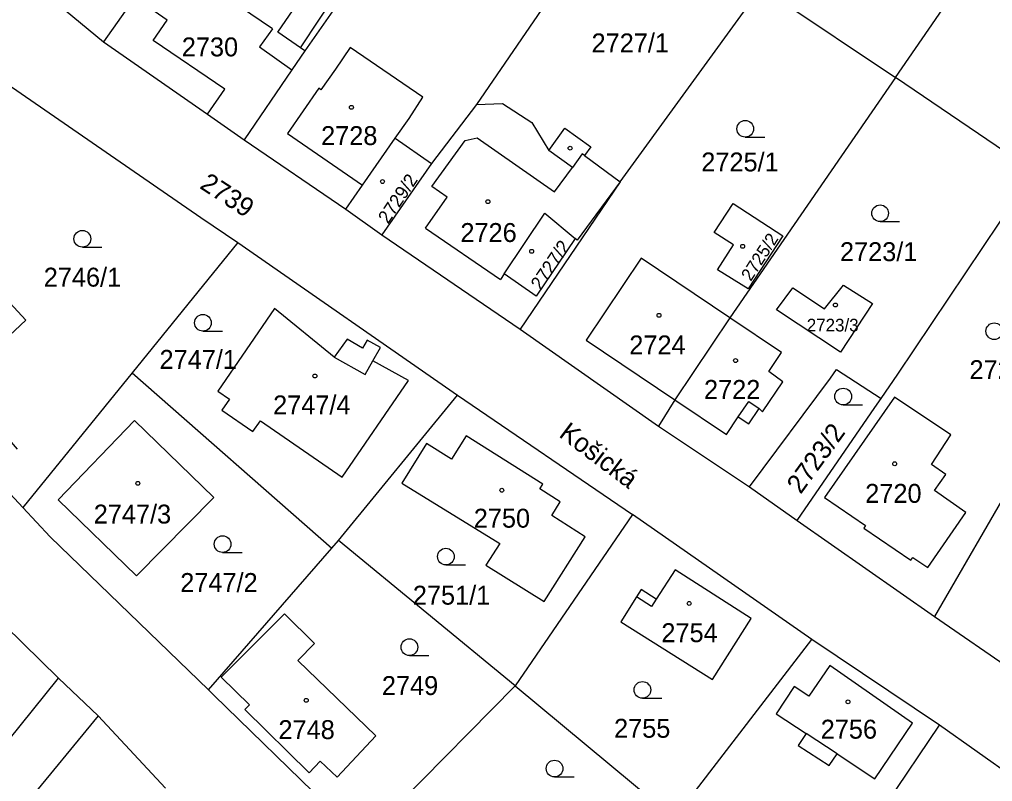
# Model space of a CAD drawing. Extents: x -869103 to -863415, y -1015889 to -1012477.
# Drawn here: x -866394.4 to -866307, y -1014734.9 to -1014666.4 of the extents above; entities that cross this region are included whole.
import ezdxf

# ---------------------------------------------------------------- set-up
doc = ezdxf.new("R2010")
doc.units = 0
for name, color, linetype in [('Hranice parcel', 7, 'Continuous'), ('Parcelní čísla', 7, 'Continuous'), ('Pop  PČ popisy', 7, 'Continuous'), ('Vnitřní kresba', 7, 'Continuous'), ('Značky budov', 7, 'Continuous'), ('Značky kultur', 7, 'Continuous')]:
    doc.layers.add(name, color=color, linetype=linetype)

msp = doc.modelspace()

# ---------------------------------------------------------------- linework, layer by layer
at = {"layer": 'Hranice parcel'}
for p, q in [((-866352.9, -1014646.59), (-866368.72, -1014669.26)), ((-866403.21, -1014654.85), (-866386.81, -1014668.44)), ((-866340.3, -1014655.05), (-866353.32, -1014674.07)), ((-866379.19, -1014657.66), (-866386.81, -1014668.44)), ((-866340.4, -1014681.04), (-866327.74, -1014663.57)), ((-866327.74, -1014663.57), (-866315.68, -1014671.67)), ((-866396.86, -1014671.28), (-866378.08, -1014684.23)), ((-866315.68, -1014671.67), (-866330.57, -1014693.25)), ((-866303.25, -1014680.11), (-866315.68, -1014671.67)), ((-866353.32, -1014674.07), (-866357.36, -1014679.39)), ((-866374.18, -1014677.25), (-866365.06, -1014683.49)), ((-866363.56, -1014681.32), (-866360.61, -1014677.11)), ((-866360.61, -1014677.11), (-866357.36, -1014679.39)), ((-866357.36, -1014679.39), (-866361.81, -1014685.79)), ((-866365.06, -1014683.49), (-866363.56, -1014681.32)), ((-866340.4, -1014681.04), (-866349.4, -1014694.28)), ((-866365.06, -1014683.49), (-866361.81, -1014685.79)), ((-866378.08, -1014684.23), (-866374.76, -1014686.5)), ((-866361.81, -1014685.79), (-866349.4, -1014694.28)), ((-866374.76, -1014686.5), (-866384.24, -1014698.2)), ((-866374.76, -1014686.5), (-866355.02, -1014700.2)), ((-866293.02, -1014686.97), (-866312.19, -1014720.09)), ((-866330.57, -1014693.25), (-866335.51, -1014700.63)), ((-866349.4, -1014694.28), (-866336.97, -1014702.98)), ((-866384.24, -1014698.2), (-866394.05, -1014710.3)), ((-866384.24, -1014698.2), (-866366.31, -1014713.95)), ((-866365.7, -1014713.25), (-866355.02, -1014700.2)), ((-866355.02, -1014700.2), (-866339.29, -1014710.92)), ((-866335.51, -1014700.63), (-866336.97, -1014702.98)), ((-866336.97, -1014702.98), (-866328.8, -1014708.43)), ((-866396.56, -1014707.62), (-866394.05, -1014710.3)), ((-866328.8, -1014708.43), (-866324.52, -1014711.48)), ((-866394.05, -1014710.3), (-866391.59, -1014712.92)), ((-866339.29, -1014710.92), (-866349.83, -1014726.33)), ((-866323.21, -1014722.15), (-866339.29, -1014710.92)), ((-866324.52, -1014711.48), (-866312.19, -1014720.09)), ((-866391.59, -1014712.92), (-866377.38, -1014726.69)), ((-866366.31, -1014713.95), (-866365.7, -1014713.25)), ((-866349.83, -1014726.33), (-866365.7, -1014713.25)), ((-866377.38, -1014726.69), (-866366.31, -1014713.95)), ((-866312.19, -1014720.09), (-866302.62, -1014726.7)), ((-866335.54, -1014738.19), (-866323.21, -1014722.15)), ((-866311.73, -1014729.85), (-866323.21, -1014722.15)), ((-866387.29, -1014729.02), (-866390.85, -1014725.62)), ((-866377.38, -1014726.69), (-866376.9, -1014727.15)), ((-866362.8, -1014739.44), (-866349.83, -1014726.33)), ((-866349.83, -1014726.33), (-866335.54, -1014738.19)), ((-866376.9, -1014727.15), (-866363.52, -1014740.17)), ((-866387.29, -1014729.02), (-866394.17, -1014737.38)), ((-866381.25, -1014735.51), (-866387.29, -1014729.02)), ((-866324.34, -1014748.5), (-866311.73, -1014729.85)), ((-866301.56, -1014737.09), (-866311.73, -1014729.85))]:
    msp.add_line(p, q, dxfattribs=at)
for points in [[(-866315.68, -1014671.67), (-866294.34, -1014640.65), (-866292.43, -1014637.83)], [(-866368.72, -1014669.26), (-866369.12, -1014669), (-866365.7, -1014663.82), (-866370.69, -1014660.31), (-866371.87, -1014662.07), (-866379.19, -1014657.66)], [(-866386.81, -1014668.44), (-866377.47, -1014674.96), (-866374.18, -1014677.25)], [(-866360.61, -1014677.11), (-866359.37, -1014675.34), (-866358.13, -1014673.44), (-866364.65, -1014668.95), (-866365.99, -1014670.9), (-866367.28, -1014672.77), (-866367.48, -1014672.63), (-866370.28, -1014676.7), (-866363.56, -1014681.32)], [(-866368.72, -1014669.26), (-866369.91, -1014670.97), (-866374.18, -1014677.25)], [(-866353.32, -1014674.07), (-866350.97, -1014673.99), (-866348.34, -1014675.69), (-866346.81, -1014678.22), (-866345.39, -1014676.21), (-866343.06, -1014677.9), (-866343.6, -1014678.68), (-866340.4, -1014681.04)], [(-866316.96, -1014700.49), (-866315.46, -1014698.31), (-866303.25, -1014680.11)], [(-866394.55, -1014705.06), (-866399.76, -1014699.03), (-866393.78, -1014693.47), (-866397.39, -1014689.6), (-866403.64, -1014682.89), (-866404.15, -1014683.37), (-866406.54, -1014680.81)], [(-866325.8, -1014685.9), (-866328.91, -1014690.64), (-866331.68, -1014688.93), (-866330.24, -1014686.71), (-866331.98, -1014685.6), (-866330.25, -1014682.98), (-866325.8, -1014685.9)], [(-866347.96, -1014691.31), (-866350.82, -1014689.3), (-866347.18, -1014683.84)], [(-866347.18, -1014683.84), (-866344.44, -1014686.14), (-866347.96, -1014691.31)], [(-866330.57, -1014693.25), (-866338.51, -1014687.9), (-866343.47, -1014695.25), (-866335.51, -1014700.63)], [(-866324.89, -1014690.56), (-866322.05, -1014692.46), (-866320.34, -1014690.31), (-866317.75, -1014691.97), (-866320.62, -1014696.35), (-866326.38, -1014692.55), (-866324.89, -1014690.56)], [(-866375.51, -1014700.55), (-866376.19, -1014701.54), (-866373.39, -1014703.48), (-866372.7, -1014702.5), (-866365.39, -1014707.56), (-866359.41, -1014698.9), (-866362.63, -1014697.12), (-866361.95, -1014695.91), (-866363.13, -1014695.25), (-866363.54, -1014695.99), (-866364.94, -1014695.17), (-866366.11, -1014696.8), (-866371.45, -1014692.43), (-866376.55, -1014699.83), (-866375.51, -1014700.55)], [(-866335.51, -1014700.63), (-866330.86, -1014703.73), (-866329.8, -1014702.14), (-866328.86, -1014702.77), (-866327.93, -1014701.39), (-866327.63, -1014701.69), (-866325.81, -1014699.01), (-866327.06, -1014698.07), (-866325.93, -1014696.38), (-866330.57, -1014693.25)], [(-866328.8, -1014708.43), (-866321.52, -1014698.68), (-866320.97, -1014697.89), (-866316.96, -1014700.49)], [(-866324.52, -1014711.48), (-866317.53, -1014701.32), (-866316.96, -1014700.49)], [(-866322.06, -1014709.41), (-866318.37, -1014711.91), (-866318.54, -1014712.16), (-866314.31, -1014715.04), (-866314.14, -1014714.79), (-866312.79, -1014715.68), (-866309.36, -1014710.74), (-866312.18, -1014708.78), (-866311.17, -1014707.32), (-866312.46, -1014706.42), (-866310.72, -1014703.78), (-866315.78, -1014700.39), (-866322.06, -1014709.41)], [(-866390.88, -1014709.62), (-866383.84, -1014716.43), (-866376.89, -1014709.41), (-866384.02, -1014702.49), (-866390.88, -1014709.62)], [(-866343.56, -1014712.94), (-866346.56, -1014711.01), (-866345.81, -1014709.8), (-866347.63, -1014708.62), (-866347.37, -1014708.2), (-866354.24, -1014703.87), (-866355.56, -1014705.97), (-866357.8, -1014704.54), (-866360.03, -1014708.11), (-866351.23, -1014713.54), (-866352.48, -1014715.47), (-866347.24, -1014718.74), (-866343.56, -1014712.94)], [(-866402.68, -1014713.62), (-866402.39, -1014713.94), (-866397.28, -1014719.33), (-866390.85, -1014725.62)], [(-866335.46, -1014715.91), (-866337.18, -1014718.53), (-866338.53, -1014717.68), (-866338.94, -1014718.33), (-866340.35, -1014720.58), (-866332.12, -1014725.74), (-866328.64, -1014720.28), (-866335.46, -1014715.91)], [(-866362.36, -1014730.82), (-866369.35, -1014724.05), (-866367.86, -1014722.52), (-866370.57, -1014719.86), (-866376.24, -1014725.55), (-866373.71, -1014728.02), (-866374.13, -1014728.45), (-866368.35, -1014734.13), (-866367.36, -1014733.09), (-866365.84, -1014734.54), (-866362.36, -1014730.82)], [(-866323.46, -1014727.26), (-866324.78, -1014726.39), (-866326.39, -1014728.83), (-866323.71, -1014730.6), (-866324.43, -1014731.69), (-866321.63, -1014733.49), (-866320.93, -1014732.44), (-866317.55, -1014734.68), (-866314.17, -1014729.67), (-866321.59, -1014724.5), (-866323.46, -1014727.26)], [(-866424.04, -1014735.88), (-866411.05, -1014750.73), (-866390.85, -1014725.62)]]:
    msp.add_lwpolyline(points, dxfattribs=at)
at = {"layer": 'Vnitřní kresba'}
for p, q in [((-866381.1, -1014666.52), (-866382.96, -1014665.23)), ((-866371.63, -1014667.28), (-866374.6, -1014665.29)), ((-866371.16, -1014667.57), (-866369.44, -1014665.11)), ((-866382.35, -1014668.33), (-866381.1, -1014666.52)), ((-866371.63, -1014667.28), (-866372.79, -1014668.89)), ((-866369.12, -1014669), (-866371.16, -1014667.57)), ((-866375.91, -1014672.72), (-866382.35, -1014668.33)), ((-866372.79, -1014668.89), (-866369.91, -1014670.97)), ((-866377.47, -1014674.96), (-866375.91, -1014672.72)), ((-866357.32, -1014681.46), (-866354.33, -1014677.32)), ((-866354.33, -1014677.32), (-866353.24, -1014677.08)), ((-866353.24, -1014677.08), (-866346.3, -1014681.94)), ((-866344.68, -1014679.74), (-866346.81, -1014678.22)), ((-866343.82, -1014678.51), (-866344.68, -1014679.74)), ((-866343.6, -1014678.68), (-866343.82, -1014678.51)), ((-866346.3, -1014681.94), (-866344.68, -1014679.74)), ((-866340.4, -1014681.04), (-866344.28, -1014686.29)), ((-866355.96, -1014682.41), (-866357.32, -1014681.46)), ((-866357.89, -1014685.2), (-866355.96, -1014682.41)), ((-866357.89, -1014685.2), (-866351.16, -1014689.8)), ((-866344.28, -1014686.29), (-866344.44, -1014686.14)), ((-866350.82, -1014689.3), (-866351.16, -1014689.8)), ((-866366.11, -1014696.8), (-866363.31, -1014698.35)), ((-866363.31, -1014698.35), (-866362.63, -1014697.12)), ((-866329.8, -1014702.14), (-866328.87, -1014700.76)), ((-866328.87, -1014700.76), (-866327.93, -1014701.39)), ((-866337.59, -1014719.18), (-866338.94, -1014718.33)), ((-866337.18, -1014718.53), (-866337.59, -1014719.18)), ((-866320.93, -1014732.44), (-866323.71, -1014730.6))]:
    msp.add_line(p, q, dxfattribs=at)
at = {"layer": 'Značky budov'}
for centre in [(-866364.547, -1014674.339), (-866344.907, -1014678.009), (-866361.757, -1014681.009), (-866352.287, -1014682.819), (-866329.407, -1014686.829), (-866348.357, -1014687.279), (-866321.077, -1014692.099), (-866336.927, -1014693.029), (-866330.047, -1014697.099), (-866367.827, -1014698.479), (-866315.757, -1014706.369), (-866383.727, -1014708.129), (-866351.037, -1014708.749), (-866334.217, -1014718.919), (-866368.607, -1014727.629), (-866319.947, -1014727.759)]:
    msp.add_circle(centre, 0.175, dxfattribs=at)
at = {"layer": 'Značky kultur'}
for p, q in [((-866329.173, -1014677.02), (-866327.423, -1014677.02)), ((-866317.063, -1014684.61), (-866315.313, -1014684.61)), ((-866388.713, -1014686.9), (-866386.963, -1014686.9)), ((-866377.883, -1014694.45), (-866376.133, -1014694.45)), ((-866320.383, -1014701.08), (-866318.633, -1014701.08)), ((-866376.113, -1014714.34), (-866374.363, -1014714.34)), ((-866356.063, -1014715.46), (-866354.313, -1014715.46)), ((-866359.343, -1014723.6), (-866357.593, -1014723.6)), ((-866338.413, -1014727.44), (-866336.663, -1014727.44)), ((-866346.303, -1014734.51), (-866344.553, -1014734.51))]:
    msp.add_line(p, q, dxfattribs=at)
for centre in [(-866329.173, -1014676.27), (-866317.063, -1014683.86), (-866388.713, -1014686.15), (-866377.883, -1014693.7), (-866306.813, -1014694.46), (-866320.383, -1014700.33), (-866376.113, -1014713.59), (-866356.063, -1014714.71), (-866359.343, -1014722.85), (-866338.413, -1014726.69), (-866346.303, -1014733.76)]:
    msp.add_circle(centre, 0.75, dxfattribs=at)

# ---------------------------------------------------------------- texts
at = {"layer": 'Parcelní čísla'}
for s, height, p in [('2730', 1.7, (-866379.78, -1014669.76)), ('2727/1', 1.7, (-866342.98, -1014669.4)), ('2728', 1.7, (-866367.27, -1014677.73)), ('2725/1', 1.7, (-866333.125, -1014680.1)), ('2726', 1.7, (-866354.76, -1014686.44)), ('2723/1', 1.7, (-866320.67, -1014688.16)), ('2746/1', 1.7, (-866392.18, -1014690.45)), ('2723/3', 1.139, (-866323.654, -1014694.479)), ('2724', 1.7, (-866339.59, -1014696.54)), ('2747/1', 1.7, (-866381.78, -1014697.84)), ('2721', 1.7, (-866309.04, -1014698.76)), ('2722', 1.7, (-866332.88, -1014700.54)), ('2747/4', 1.7, (-866371.58, -1014701.93)), ('2720', 1.7, (-866318.4, -1014709.88)), ('2747/3', 1.7, (-866387.69, -1014711.74)), ('2750', 1.7, (-866353.56, -1014712.11)), ('2747/2', 1.7, (-866379.92, -1014717.89)), ('2751/1', 1.7, (-866359.03, -1014719.03)), ('2754', 1.7, (-866336.71, -1014722.4)), ('2749', 1.7, (-866361.81, -1014727.15)), ('2748', 1.7, (-866371.1, -1014731.11)), ('2755', 1.7, (-866340.96, -1014730.99)), ('2756', 1.7, (-866322.4, -1014731.07))]:
    msp.add_text(s, height=height, dxfattribs=at).set_placement(p)
for s, height, rotation, p in [('2739', 1.7, 327, (-866378.262, -1014681.552)), ('2729/2', 1.19, 56, (-866361.256, -1014684.882)), ('2725/2', 1.139, 57, (-866328.678, -1014690.037)), ('2727/2', 1.19, 56, (-866347.546, -1014690.842)), ('2723/2', 1.7, 54, (-866324.202, -1014709.169))]:
    msp.add_text(s, height=height, rotation=rotation, dxfattribs=at).set_placement(p)
at = {"layer": 'Pop  PČ popisy'}
msp.add_text('Košická', height=1.7, rotation=323, dxfattribs=at).set_placement((-866346.001, -1014703.878))

doc.saveas('drawing.dxf')
